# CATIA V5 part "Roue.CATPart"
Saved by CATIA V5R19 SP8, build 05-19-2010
Part number: Roue
Bounding box of the stored display mesh (mm): x -174.761 to 174.761, y -58.105 to 58.105, z -174.759 to 174.759
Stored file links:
  J:\Travail\2e année\IAO\Projet\Roue.CATPart
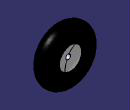
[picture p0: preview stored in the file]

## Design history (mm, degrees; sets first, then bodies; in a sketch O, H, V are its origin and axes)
Set1
  Line1: type PtPt, FirstPoint vertex [element of Sketch1 | element of Sketch1], SecondPoint vertex [element of Sketch1 | element of Sketch1]
Body1 (main body)
  Sketch1 on yz-plane, origin (0, 0, 0), H (0, 1, 0), V (0, 0, 1)
    construction line L1 (-49.9711, 0) -> (98.3128, 0)
    point P1 (-49.9711, 0)
    arc A1 centre (0, 116.8623) radius 58.1377 from (34.4081, 70) to (-34.4081, 70) ccw
    point P3 (0, 116.8623)
    spline S1 through (34.4081, 70) (23.6803, 44.1973) (20, 15.881)
    axis line L2 (0, 116.8623) -> (0, -33.4046)
    spline S2 through (-34.4081, 70) (-23.6803, 44.1973) (-20, 15.881)
    point P5 (-34.4081, 70)
    point P6 (34.4081, 70)
    line L3 (20, 15.881) -> (20, 0)
    point P7 (20, 15.881)
    point P8 (20, 0)
    point P9 (-20, 0)
    point P10 (-20, 15.881)
    line L4 (-20, 15.881) -> (-20, 0)
    line L5 (20, 0) -> (-20, 0)
    point P11 (34.4081, 70)
    point P12 (20, 15.881)
    point P13 (-20, 15.881)
    point P14 (-34.4081, 70)
    point P15 (23.6803, 44.1973)
    point P16 (-23.6803, 44.1973)
    distance P11 L1 = 70
    distance A1 L1 = 175
    distance P8 L2 = 20
    coincidence: P1 H, P3 V, P11 A1, P14 P5, P11 P6, P12 P7, P8 L1
    horizontal: L1 H, L5 H
    vertical: L2 V, L3 V
    symmetry: S1 S2 L2, P12 P13 L2, P11 P14 L2, P15 P16 L2, P8 P9 L2, P7 P10 L2, L3 L4 L2
    tangency: L3 S1
  Shaft1: profile Sketch1, axis Line1, angle 360
  Sketch2 on zx-plane, origin (0, 0, 0), H (-1, 0, 0), V (0, 0, 1)
    circle A1 centre (0, 0) radius 15
    radius A1 = 15
  Pocket1: profile Sketch2, direction (0, -1, 0), through (limit type 6), opposite side through (limit type 6)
